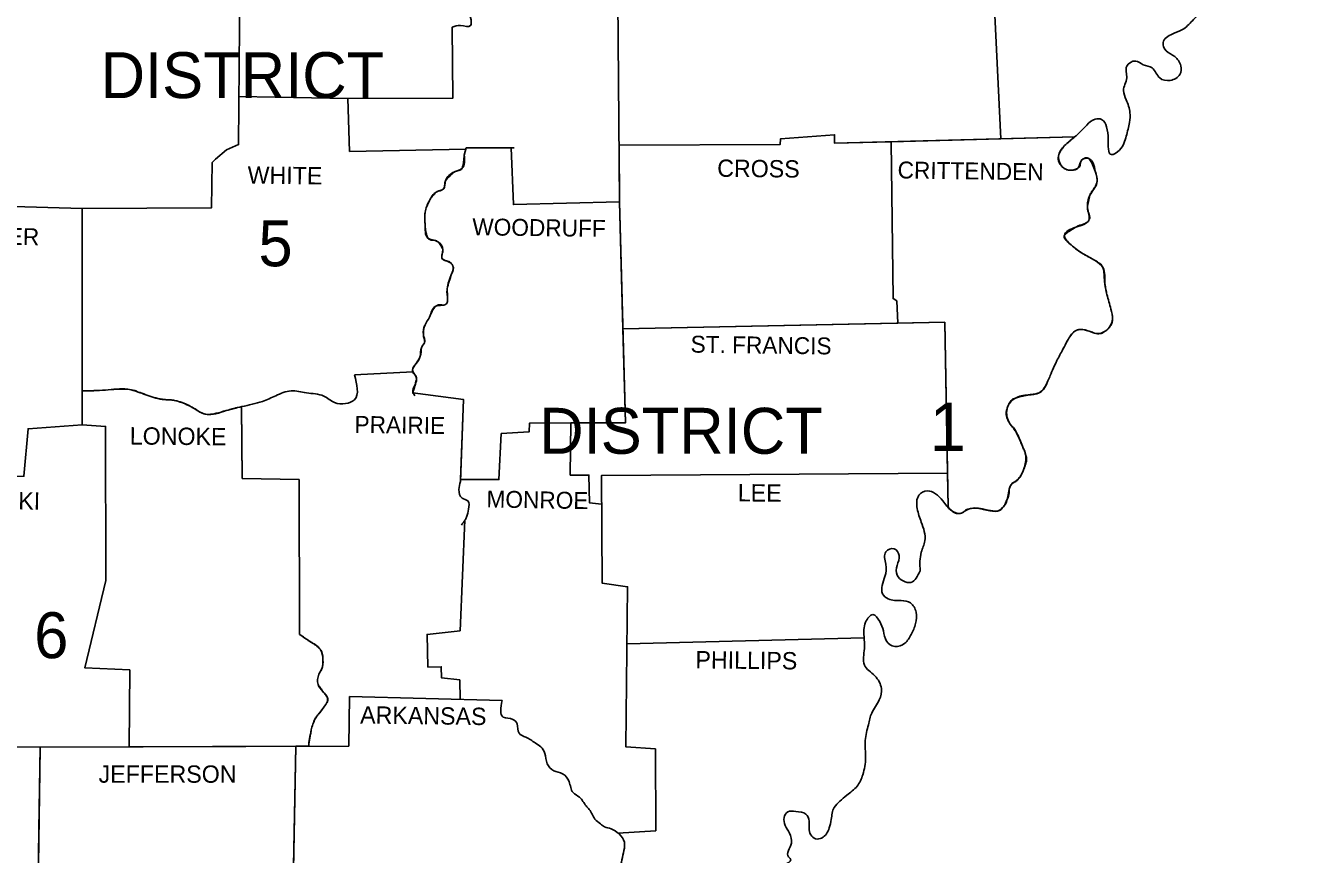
# Model space of a CAD drawing. Extents: x -24122 to 24238, y -8840 to 11381.
# Drawn here: x 13643 to 16747, y 7032 to 9043 of the extents above; entities that cross this region are included whole.
import ezdxf

# ---------------------------------------------------------------- set-up
doc = ezdxf.new("R2010")
doc.units = 0
for name, color, linetype in [('R_Annotation', 7, 'Continuous'), ('R_Border', 7, 'Continuous'), ('R_Grid', 7, 'Continuous'), ('S_AREA_CALC', 7, 'Continuous')]:
    doc.layers.add(name, color=color, linetype=linetype)

msp = doc.modelspace()

# ---------------------------------------------------------------- linework, layer by layer
at = {"layer": 'R_Annotation'}
for p, q in [((15082.5, 8752.4), (15083.6, 8615.5)), ((15747, 8380.6), (15742.1, 8761.1)), ((15083.6, 8615.5), (15092.1, 8307.2)), ((15092.1, 8307.2), (15083.6, 8615.5)), ((15092.1, 8307.2), (15758.9, 8320.6)), ((15758.9, 8320.6), (15872.2, 8322.9)), ((14581.7, 8202.5), (14582.7, 8202.6)), ((13894.8, 7292.5), (14299.1, 7294.1)), ((14291.1, 6910.1), (14299.1, 7294.1)), ((14299.1, 7294.1), (14329.5, 7294.2))]:
    msp.add_line(p, q, dxfattribs=at)
for points in [[(15742.1, 8761.1), (15605.1, 8757.3), (15605.1, 8777.9), (15474, 8768.1), (15473.1, 8754.4), (15082.5, 8752.4)], [(16188, 8773.3), (16008.6, 8768.4), (15742.1, 8761.1)], [(15742.1, 8761.1), (15747, 8380.6), (15755.8, 8374.8), (15758.9, 8320.6)], [(16188, 8773.3), (16188, 8773.3)], [(14711.9, 8746.6), (14710.8, 8742.8), (14707, 8728.9)], [(14821.2, 8746.6), (14821.2, 8746.6), (14711.9, 8746.6)], [(15083.6, 8615.5), (14826.3, 8608.6), (14821.2, 8746.6)], [(15758.9, 8320.6), (15755.8, 8374.8), (15747, 8380.6)], [(15872.2, 8322.9), (15878.9, 7957), (15880.4, 7874.8)], [(14698.3, 7941.3), (14791.1, 7941.3), (14797, 8052.9), (14864.5, 8056.8), (14865.5, 8078.3), (14965.3, 8078.7), (15098.3, 8079.3), (15092.1, 8307.2)], [(14582.7, 8202.6), (14581.8, 8202.2)], [(13780.4, 8156.5), (13780.4, 8156.5), (13780.4, 8074.4)], [(14582.7, 8151.7), (14705, 8136), (14698.3, 7941.3)], [(14307.8, 7565.6), (14306.8, 7941.3), (14168.8, 7944.3), (14166.9, 8118.2)], [(13419.4, 7948.2), (13639.5, 7949.2), (13649.3, 8064.6), (13780.4, 8074.4)], [(13780.4, 8074.4), (13837.2, 8070.5), (13838.1, 7696.7), (13787.3, 7484.4), (13895.9, 7479.5), (13894.8, 7292.5)], [(13780.4, 8074.4), (13837.2, 8070.5), (13838.1, 7696.7), (13787.3, 7484.4), (13895.9, 7479.5), (13894.8, 7292.5)], [(14698.3, 7941.3), (14698.3, 7941.3)], [(14299.1, 7294.1), (13894.8, 7292.5), (13678.7, 7291.7)], [(13678.7, 7291.7), (13675.7, 7092.1), (13672.8, 6894.4), (13650.3, 6893.5)], [(13894.8, 7292.5), (13678.7, 7291.7)]]:
    msp.add_lwpolyline(points, dxfattribs=at)
for points in [[(16237.2, 8689.8), (16230.8, 8705.9), (16226.6, 8713.3), (16224.2, 8716.8), (16221.5, 8720.1), (16218, 8722), (16213.3, 8721.7), (16208.6, 8719.8), (16204.9, 8717.2), (16202.4, 8712.8), (16201.1, 8707.3), (16199.6, 8701.9), (16196.1, 8697.6), (16191.9, 8695.2), (16187.8, 8693.4), (16183.6, 8692.2), (16179.5, 8691.8), (16174.1, 8692), (16168.7, 8693.2), (16163.3, 8695.6), (16157.9, 8699.6), (16156.2, 8701.3), (16154.6, 8703.1), (16151.8, 8706.9), (16148.4, 8714.8), (16147.5, 8722.7), (16149.1, 8729.9), (16152.2, 8736.3), (16156.1, 8742.7), (16165.8, 8754.4), (16176.9, 8764.1), (16188, 8773.3)], [(14707, 8728.9), (14706.4, 8720.8), (14705.6, 8712.7), (14704.3, 8704.6), (14703.3, 8700.6), (14702.7, 8698.6), (14702.1, 8696.7), (14698.9, 8693.1), (14693.9, 8691.3), (14688.3, 8690.1), (14685.7, 8689.2), (14683.5, 8687.9), (14672, 8677.8), (14662, 8666.3), (14660.1, 8661.7), (14659.7, 8656.4), (14659.1, 8651.2), (14657.1, 8646.8), (14655.3, 8645.3), (14653.2, 8644.2), (14648.4, 8642.8), (14643.5, 8641.4), (14639.4, 8638.9), (14634.8, 8634.3), (14630.5, 8629.4), (14626.4, 8624.1), (14622.8, 8618.4), (14616.1, 8604.5), (14612.1, 8590), (14611.3, 8575.4), (14612.1, 8560.7), (14612.7, 8552.2), (14613.9, 8543.8), (14615.8, 8535.6), (14617.2, 8531.5), (14618.9, 8527.4), (14623.5, 8523.5), (14630.3, 8522.4), (14637.5, 8521.6), (14643.4, 8518.6), (14645.3, 8516.4), (14647.1, 8514.1), (14650.3, 8509.3), (14655.1, 8499), (14655.4, 8494), (14653.9, 8488.6), (14652.6, 8483.3), (14653.1, 8478.5), (14657.7, 8474.2), (14664.5, 8471.8), (14671.5, 8469.4), (14676.6, 8464.8), (14678.3, 8461.9), (14679.8, 8458.9), (14680.7, 8456), (14680.5, 8453), (14676.6, 8440.3), (14665.9, 8404.1), (14665.1, 8398.1), (14665.6, 8392), (14666.5, 8385.8), (14666.8, 8379.7), (14666.4, 8374.2), (14665.8, 8371.5), (14664.9, 8368.9), (14659.8, 8365.2), (14652, 8365.1), (14644, 8365.2), (14638.5, 8362), (14622.8, 8335.6), (14612.1, 8317), (14610.7, 8314), (14608.7, 8304.9), (14608.3, 8298.7), (14608.1, 8292.6), (14608.6, 8288.2), (14609.8, 8283.8), (14611, 8279.4), (14611.1, 8275), (14609.7, 8271.3), (14607.4, 8268), (14604.9, 8264.7), (14603.2, 8261.3), (14602.5, 8256.2), (14602.3, 8250.9), (14601.9, 8245.6), (14600.3, 8240.7), (14590.5, 8223.1), (14581.7, 8206.5), (14581.7, 8202.5)], [(16077.6, 8147.3), (16089.5, 8148.8), (16101.2, 8151.7), (16103.3, 8152.7), (16105.3, 8153.9), (16108.8, 8156.7), (16114.5, 8164), (16118.9, 8172.4), (16122.7, 8181), (16133.5, 8206.5), (16144.2, 8230), (16158.9, 8257.4), (16173.6, 8284.8), (16182.1, 8296.5), (16194.1, 8304.3), (16197.2, 8305.1), (16200.4, 8305.5), (16206.9, 8305.1), (16219.6, 8302.4), (16225, 8300.8), (16230.3, 8298.8), (16235.7, 8296.8), (16241.1, 8295.5), (16246.2, 8295.3), (16251.4, 8296.1), (16256.5, 8298.1), (16261.6, 8301.4), (16265.5, 8304.6), (16269, 8308), (16274.7, 8315.1), (16278.2, 8322.6), (16279.3, 8330.7), (16278.9, 8336.9), (16278, 8343), (16275.3, 8355.2), (16265.6, 8390.4), (16263, 8403.1), (16260.7, 8415.9), (16259.5, 8425.9), (16259, 8436), (16258.1, 8446), (16255.8, 8456), (16254.5, 8458.8), (16252.7, 8461.4), (16248.1, 8465.7), (16237.2, 8472.6), (16229.9, 8476.9), (16222.5, 8480.9), (16215.1, 8484.9), (16207.8, 8489.2), (16192.9, 8499.4), (16178.5, 8510.8), (16166, 8522.5), (16162.2, 8528.8), (16162.8, 8534.2), (16165.3, 8537), (16168.2, 8539.6), (16175.1, 8544.5), (16182.7, 8549.2), (16190.2, 8553.8), (16194.1, 8555.9), (16198.2, 8557.6), (16206.6, 8560.4), (16214.6, 8564.1), (16221.5, 8570.4), (16222.6, 8572.2), (16223.4, 8574.1), (16223.9, 8577.8), (16222.2, 8585.4), (16219.5, 8593.2), (16218.6, 8600.8), (16220.9, 8616), (16224.5, 8631.1), (16228.1, 8639.1), (16233.2, 8646.4), (16238, 8653.7), (16241.1, 8661.4), (16237.2, 8689.8)], [(14581.8, 8202.2), (14584.4, 8198.4), (14587.9, 8194.6), (14590.7, 8190.8), (14591.5, 8186.9), (14590.1, 8180.1), (14588.6, 8173.2), (14587.1, 8167.8), (14585.3, 8162.4), (14582.7, 8151.7)], [(14166.9, 8118.2), (14129.7, 8108.6), (14117.5, 8105.3), (14105.2, 8102.1), (14086.8, 8099.6), (14080.8, 8099.8), (14078.2, 8100.2), (14075.7, 8100.9), (14061.5, 8108.1), (14052.2, 8114.2), (14047.5, 8117), (14042.6, 8119.4), (14010.3, 8132.1), (13999, 8134.3), (13987.3, 8135.1), (13975.7, 8135.8), (13970, 8136.6), (13964.3, 8138), (13925.2, 8150.7), (13921, 8152.2), (13916.7, 8153.8), (13908.3, 8157.1), (13891, 8160.5), (13837.2, 8158.5), (13780.4, 8156.5)], [(14329.5, 7294.2), (14332.6, 7314), (14334.3, 7323.9), (14336.1, 7333.7), (14340.1, 7347.7), (14342.8, 7354.5), (14345.9, 7361.1), (14347.8, 7364.5), (14350, 7367.6), (14354.8, 7373.5), (14359.9, 7379.3), (14362.3, 7382.4), (14364.5, 7385.6), (14366.7, 7388.8), (14369, 7392.1), (14373.5, 7399), (14376.2, 7405.7), (14375.3, 7412), (14374.7, 7412.9), (14374.2, 7413.9), (14370.2, 7419.4), (14367.3, 7423), (14364.5, 7426.7), (14358.5, 7435.4), (14355.5, 7439.8), (14354.1, 7442), (14352.8, 7444.3), (14351.3, 7456.3), (14352.8, 7462.7), (14354.7, 7468.8), (14356.5, 7472.7), (14358.7, 7476.5), (14360.9, 7480.3), (14362.6, 7484.4), (14363.6, 7489), (14364.3, 7493.7), (14364.5, 7498.4), (14364.5, 7503), (14364.4, 7506.4), (14364.3, 7509.9), (14363.5, 7516.7), (14361.6, 7523.3), (14357.7, 7529.4), (14356.2, 7531.1), (14354.6, 7532.6), (14351.6, 7535.4), (14345.3, 7540.3), (14338.8, 7544.6), (14332.2, 7549), (14307.8, 7565.6)]]:
    msp.add_spline(points, degree=3, dxfattribs=at)
msp.add_open_spline([(15880.4, 7874.8), (15883.1, 7871.8), (15885.8, 7868.9), (15888.9, 7866), (15894.4, 7860.8), (15902.9, 7858.4), (15909.4, 7859.1), (15916.4, 7859.9), (15922.4, 7868.4), (15930, 7869.9), (15937, 7871.3), (15944.4, 7872.8), (15951.5, 7871.9), (15960, 7870.8), (15968.4, 7868.3), (15976.9, 7867), (15984.7, 7865.7), (15992.6, 7864.4), (16000.4, 7865), (16005.1, 7865.4), (16008.9, 7868.9), (16012.2, 7872.8), (16018.3, 7880.3), (16021.5, 7888.1), (16024.9, 7896.3), (16029, 7906.3), (16027.5, 7918.2), (16032.7, 7927.6), (16036.4, 7934.3), (16045.7, 7936.1), (16050.3, 7942.3), (16055.9, 7949.9), (16060.6, 7957.7), (16064, 7966.8), (16068.1, 7977.6), (16071.9, 7989.4), (16068.9, 8000), (16066.4, 8008.9), (16062.8, 8017.7), (16059.1, 8026.5), (16054.7, 8036.8), (16050.2, 8046.8), (16045.4, 8056.8), (16041.1, 8065.8), (16032.7, 8072.5), (16027.8, 8081.2), (16021.9, 8091.7), (16020.4, 8106.1), (16024.9, 8117.4), (16028.4, 8126.3), (16034.3, 8135.7), (16043.5, 8139), (16053.8, 8142.7), (16064.3, 8144.5), (16074.8, 8146.8), (16075.7, 8147), (16076.7, 8147.2), (16077.6, 8147.3)], degree=3, dxfattribs=at)
at = {"layer": 'S_AREA_CALC'}
msp.add_line((14711.9, 8746.6), (14828.3, 8746.6), dxfattribs=at)
for points in [[(13715.8, 10314.9), (13717.8, 10076.2), (13701.2, 10075.2), (13704.1, 9831.6), (13635.6, 9821.8), (13641.5, 9756.3), (13665, 9725.9), (13663, 9648.7), (13529.9, 9643.8), (13525, 9524.4), (13403.7, 9520.5), (13397.9, 9375.7), (13404.7, 9363.9), (13407.6, 9133), (13617, 9119.3), (13614.1, 8603.7), (13780.4, 8598.8), (13780.4, 8074.4), (13649.3, 8064.6), (13639.5, 7949.2), (13419.4, 7948.2)], [(14615, 10322.8), (14612.1, 10299.3), (14631.6, 10296.4), (14630.6, 10284.6), (14653.1, 10279.7), (14655.1, 10264.1), (14665.9, 10257.2), (14668.8, 10210.3), (14724.6, 10204.4), (14724.6, 10162.3), (14745.1, 10159.4), (14745.1, 10142.7), (14762.7, 10137.9), (14761.8, 10081.1), (14777.4, 10078.2), (14781.3, 9950), (14698.2, 9942.2), (14699.1, 9914.8), (14673.7, 9913.8), (14682.5, 9408.9), (15076.8, 9400.1), (15083.6, 8615.5), (14826.3, 8608.6), (14821.2, 8746.6)], [(15971.8, 9598.7), (15988.7, 9169.2), (16008.6, 8768.4)], [(13617, 9119.3), (14119.9, 9116.4), (14163, 9136.9), (14160, 8754.4), (14130.7, 8741.7), (14104.3, 8719.2), (14095.5, 8710.4), (14094.5, 8600.8), (13780.4, 8598.8)], [(14677.6, 9039.1), (14679.6, 8866.9), (14425.2, 8865.9), (14160.9, 8870.9)], [(14425.2, 8865.9), (14429.1, 8737.8), (14710.8, 8742.8)], [(15082.5, 8752.4), (15473.1, 8754.4), (15474, 8768.1), (15605.1, 8777.9), (15605.1, 8757.3), (16188, 8773.3)], [(15742.1, 8761.1), (15747, 8380.6), (15755.8, 8374.8), (15758.9, 8320.6)], [(14711.9, 8746.6), (14707, 8728.9)], [(15083.6, 8615.5), (15098.3, 8079.3), (14865.5, 8078.3), (14864.5, 8056.8), (14797, 8052.9), (14791.1, 7941.3), (14698.3, 7941.3)], [(15092.1, 8307.2), (15872.2, 8322.9)], [(15872.2, 8322.9), (15880.4, 7874.7)], [(14440.8, 8195.7), (14582.7, 8202.6)], [(14582.7, 8151.7), (14705, 8136), (14698.2, 7936.4)], [(14166.9, 8119.4), (14168.8, 7944.3), (14306.8, 7941.3), (14307.8, 7565.6)], [(13780.4, 8074.4), (13837.2, 8070.5), (13838.1, 7696.7), (13787.3, 7484.4), (13895.9, 7479.5), (13894.8, 7292.5)], [(14965.3, 8078.7), (14964.3, 7952.1), (15009.3, 7952.1), (15011.2, 7884.6), (15040.1, 7881.6)], [(15079.7, 7083.2), (15171.7, 7089.1), (15170.7, 7287.8), (15099.3, 7292.6), (15103.2, 7681.1), (15041.6, 7689.9), (15039.6, 7951.1), (15878.9, 7957)], [(14708.9, 7842.5), (14697.2, 7574.4), (14616.9, 7565.6), (14618.9, 7486.4), (14651.2, 7487.3), (14652.2, 7460), (14696.2, 7455.1), (14697.6, 7407.8)], [(15101.8, 7543), (15676.7, 7557.3)], [(14798.9, 7405.2), (14429.1, 7414.9), (14427.1, 7294.6), (13678.7, 7291.7)], [(13115.1, 7162.5), (13169.9, 7170.3), (13173.8, 7203.6), (13206.1, 7209.5), (13208, 7229), (13436, 7235.9), (13444.8, 7295.6), (13678.7, 7291.7)], [(14299.1, 7294.1), (14291.1, 6910.1), (14427.1, 6899.3)], [(13678.7, 7289.7), (13672.8, 6894.4), (13650.3, 6893.5), (13647.3, 6647.9)]]:
    msp.add_lwpolyline(points, dxfattribs=at)
for points in [[(16610, 9631), (16620.7, 9632), (16654, 9596.8), (16668.7, 9567.4), (16690.2, 9550.8), (16714.7, 9542), (16733.2, 9519.5), (16746, 9495), (16739.1, 9473.5), (16711.7, 9471.6), (16681.4, 9466.7), (16652, 9467.6), (16628.6, 9448.1), (16650.1, 9421.7), (16678.4, 9397.2), (16686.3, 9370.8), (16670.6, 9345.3), (16639.3, 9331.6), (16609, 9319.9), (16581.6, 9296.4), (16568.9, 9273.9), (16538.5, 9264.1), (16507.2, 9255.3), (16479.8, 9252.4), (16448.5, 9246.5), (16418.2, 9231.8), (16405.5, 9206.4), (16409.4, 9170.2), (16408.4, 9132.1), (16440.7, 9119.3), (16469.1, 9118.4), (16496.5, 9103.7), (16493.5, 9082.2), (16473, 9054.8), (16448.5, 9033.2), (16424.1, 9022.5), (16401.6, 9001.9), (16409.4, 8981.4), (16429.9, 8967.7), (16444.6, 8945.2), (16442.7, 8924.6), (16419.2, 8910), (16393.7, 8915.8), (16375.1, 8940.3), (16353.6, 8948.1), (16335, 8956.9), (16313.5, 8944.2), (16313.5, 8915.8), (16305.7, 8885.5), (16312.5, 8863), (16321.3, 8831.7), (16320.4, 8808.2), (16312.5, 8774.9), (16295.9, 8740.7), (16276.3, 8729.9), (16268.5, 8767.1), (16264.6, 8797.4), (16252.8, 8815), (16237.2, 8816), (16216.6, 8801.3), (16194.1, 8778.8), (16165.8, 8754.4), (16149.1, 8729.9), (16157.9, 8699.6), (16179.5, 8691.8), (16196.1, 8697.6), (16204.9, 8717.2), (16221.5, 8720.1), (16237.2, 8689.8)], [(14858.1, 9405.1), (14841, 9361), (14827.3, 9331.6), (14818.5, 9306.2), (14799.9, 9291.5), (14794, 9277.8), (14777.4, 9272), (14764.7, 9252.4), (14758.8, 9234.8), (14745.1, 9227), (14738.3, 9205.4), (14725.5, 9193.7), (14726.5, 9174.1), (14711.9, 9160.4), (14700.1, 9144.8), (14700.1, 9123.2), (14705, 9094.9), (14714.8, 9078.2), (14723.6, 9056.7), (14722.6, 9043), (14698.2, 9043), (14677.6, 9039.1)], [(14707, 8728.9), (14702.1, 8696.7), (14683.5, 8687.9), (14662, 8666.3), (14657.1, 8646.8), (14639.4, 8638.9), (14622.8, 8618.4), (14612.1, 8590), (14612.1, 8560.7), (14618.9, 8527.4), (14643.4, 8518.6), (14655.1, 8499), (14653.1, 8478.5), (14676.6, 8464.8), (14680.5, 8453), (14676.6, 8440.3), (14665.9, 8404.1), (14666.8, 8379.7), (14664.9, 8368.9), (14638.5, 8362), (14622.8, 8335.6), (14612.1, 8317), (14608.1, 8292.6), (14611.1, 8275), (14603.2, 8261.3), (14600.3, 8240.7), (14590.5, 8223.1), (14581.7, 8206.5), (14591.5, 8186.9), (14588.6, 8173.2), (14582.7, 8151.7), (14587.6, 8144.8)], [(16237.2, 8689.8), (16241.1, 8661.4), (16224.5, 8631.1), (16218.6, 8600.8), (16221.5, 8570.4), (16190.2, 8553.8), (16162.8, 8534.2), (16178.5, 8510.8), (16207.8, 8489.2), (16237.2, 8472.6), (16255.8, 8456), (16260.7, 8415.9), (16265.6, 8390.4), (16275.3, 8355.2), (16279.3, 8330.7), (16261.6, 8301.4), (16241.1, 8295.5), (16219.6, 8302.4), (16194.1, 8304.3), (16173.6, 8284.8), (16158.9, 8257.4), (16144.2, 8230), (16133.5, 8206.5), (16122.7, 8181), (16101.2, 8151.7), (16074.8, 8146.8), (16043.5, 8139), (16024.9, 8117.4), (16027.8, 8081.2), (16045.4, 8056.8), (16059.1, 8026.5), (16068.9, 8000), (16064, 7966.8), (16050.3, 7942.3), (16032.7, 7927.6), (16024.9, 7896.3), (16012.2, 7872.8), (16000.4, 7865), (15976.9, 7867), (15951.5, 7871.9), (15930, 7869.9), (15909.4, 7859.1), (15888.9, 7866), (15867.4, 7889.5), (15849.7, 7907.1), (15830.2, 7913.9), (15809.6, 7903.2), (15805.7, 7870.9), (15815.5, 7837.6), (15824.3, 7792.6), (15815.5, 7765.2), (15812.6, 7720.2)], [(13780, 8156.5), (13837.2, 8158.5), (13891, 8160.5), (13925.2, 8150.7), (13964.3, 8138), (14010.3, 8132.1), (14042.6, 8119.4), (14080.8, 8099.8), (14129.7, 8108.6), (14167.9, 8118.4), (14217.8, 8131.1), (14250, 8144.8), (14287.2, 8156.6), (14324.4, 8151.7), (14366.5, 8143.9), (14392.9, 8128.2), (14440.8, 8135.1), (14440.8, 8195.7)], [(14698.2, 7936.4), (14694.2, 7916.9), (14702.1, 7896.3), (14715.8, 7889.5), (14717.7, 7869.9), (14712.8, 7850.3), (14708.9, 7842.5), (14700.1, 7830.8)], [(15812.6, 7720.2), (15790.1, 7691.8), (15756.8, 7709.4), (15756.8, 7732.9), (15761.7, 7757.4), (15749.9, 7773), (15729.4, 7766.2), (15729.4, 7735.9), (15727.4, 7706.5), (15721.6, 7664.4), (15735.3, 7651.7), (15766.6, 7647.8), (15789.1, 7641.9), (15802.8, 7619.4), (15801.8, 7592), (15791, 7565.6), (15775.4, 7544.1), (15750.9, 7536.3), (15731.4, 7549), (15723.5, 7574.4), (15714.7, 7596.9), (15698.1, 7613.6), (15680.5, 7595), (15676.6, 7560.7), (15677.5, 7531.4), (15677.5, 7491.3), (15703, 7464.8), (15718.6, 7434.5), (15713.7, 7407.1), (15695.2, 7374.8), (15687.3, 7346.5), (15679.5, 7308.3), (15680.5, 7266.2), (15673.6, 7225.1), (15659.9, 7197.7), (15634.5, 7175.2), (15617.9, 7160.6), (15604.2, 7145.9), (15597.3, 7116.5), (15592.4, 7096), (15573.8, 7071.5), (15559.2, 7069.6), (15547.4, 7079.4), (15543.5, 7096), (15543.5, 7112.6), (15535.7, 7129.3), (15511.2, 7136.1), (15491.6, 7135.1), (15482.8, 7121.4), (15495.6, 7083.3), (15500.4, 7058.8), (15493.6, 7025.5), (15497.5, 7021.6), (15462.3, 7003), (15433.9, 7000.1), (15410.4, 6993.3), (15387.9, 6978.6), (15377.2, 6957.1), (15361.5, 6939.4), (15347.8, 6922.8), (15329.2, 6915), (15308.7, 6918.9), (15281.3, 6921.8), (15265.6, 6902.3), (15270.5, 6873.9), (15289.1, 6857.3), (15316.5, 6849.4), (15344.9, 6851.4), (15372.3, 6854.3), (15397.7, 6840.6), (15392.8, 6814.2), (15368.4, 6801.5), (15332.2, 6797.6), (15302.8, 6800.5), (15267.6, 6792.7), (15250, 6770.2), (15259.8, 6735.9), (15297.9, 6722.2), (15315.5, 6689.9), (15316.5, 6659.6), (15303.8, 6619.5), (15286.2, 6600.9), (15251.9, 6593.1), (15225.5, 6588.2), (15221.6, 6543.2), (15209.9, 6520.7), (15189.3, 6513.8), (15160, 6528.5), (15142.4, 6535.4), (15120.8, 6545.1), (15093.4, 6561.8), (15072.9, 6558.8), (15078.8, 6515.8), (15080.7, 6513.8), (15104.2, 6481.5), (15127.7, 6456.1), (15138.4, 6425.8)], [(14307.8, 7565.6), (14332.2, 7549), (14357.7, 7529.4), (14364.5, 7503), (14362.6, 7484.4), (14354.7, 7468.8), (14352.8, 7444.3), (14364.5, 7426.7), (14375.3, 7412), (14364.5, 7385.6), (14345.9, 7361.1), (14336.1, 7333.7), (14329.3, 7292.6)], [(14798.9, 7405.2), (14801.9, 7365), (14825.3, 7359.2), (14835.1, 7348.4), (14840, 7325.9), (14856.7, 7316.1), (14879.2, 7302.4), (14892.9, 7292.6), (14902.6, 7277), (14908.5, 7251.6), (14924.2, 7234.9), (14945.7, 7227.1), (14961.3, 7208.5), (14971.1, 7182.1), (14986.8, 7170.3), (15002.4, 7149.8), (15010.3, 7141), (15024, 7117.5), (15037.7, 7105.8), (15047.4, 7098.9), (15063.1, 7094), (15082.7, 7081.3), (15095.4, 7061.7), (15095.4, 7047.1), (15090.5, 7024.6), (15086.6, 7001.1), (15084.6, 6974.7), (15082.7, 6951.2), (15091.5, 6931.6), (15086.6, 6902.3), (15076.8, 6886.6), (15075.8, 6865.1), (15072.9, 6832.8), (15069, 6814.2), (15060.2, 6783.9), (15047.4, 6768.2)]]:
    msp.add_spline(points, degree=3, dxfattribs=at)

# ---------------------------------------------------------------- texts
at = {"layer": 'R_Border'}
for s, height, rotation, p in [('WHITE', 42.07, 359.3139, (14181.6, 8659.5)), ('CROSS', 42.06, 359.3839, (15320.4, 8676.1)), ('CRITTENDEN', 41.09, 359.213, (15757.8, 8672.2)), ('WOODRUFF', 41.08, 359.2748, (14726.5, 8534.2)), ('FAULKNER', 41.09, 359.2486, (13383.2, 8513.7)), ('ST. FRANCIS', 41.081, 359.2216, (15255.8, 8249.5)), ('PRAIRIE', 41.09, 359.2116, (14440.8, 8054.8)), ('LONOKE', 42.07, 359.4974, (13895.9, 8026.5)), ('PULASKI', 42.07, 359.053, (13440.9, 7871.9)), ('MONROE', 41.08, 359.0331, (14760.8, 7873.8)), ('LEE', 42.07, 359.4327, (15370.3, 7888.5)), ('PHILLIPS', 42.06, 359.3179, (15267.6, 7483.4)), ('ARKANSAS', 42.06, 359.2678, (14454.5, 7349.4))]:
    msp.add_text(s, height=height, rotation=rotation, dxfattribs=at).set_placement(p)
msp.add_text('JEFFERSON', height=42.07, dxfattribs=at).set_placement((13820.5, 7205.6))
at = {"layer": 'R_Grid'}
for s, height, p in [('DISTRICT', 111.54, (13825.4, 8866.9)), ('5', 111.5, (14208, 8458.9)), ('DISTRICT', 111.54, (14888.9, 8003.9)), ('DISTRICT 6', 111.54, (12935.1, 7507.9))]:
    msp.add_text(s, height=height, dxfattribs=at).set_placement(p)
at = {"layer": 'S_AREA_CALC'}
msp.add_text('1', height=117.4, dxfattribs=at).set_placement((15836, 8010.8))

doc.saveas('drawing.dxf')
